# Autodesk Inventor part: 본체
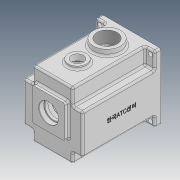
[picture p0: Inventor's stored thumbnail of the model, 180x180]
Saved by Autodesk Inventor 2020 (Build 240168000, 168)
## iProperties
Created: 2022-01
Part Number: 본체
Material: 일반
Document SubType Name: Modeling
Designer: user
Density: 1 g/cm^3
Appearance: 기본값
Author: user
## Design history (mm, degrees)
sketch "스케치2"
  geometry: L1 (-49, 55)-(49, 55); L2 (49, 55)-(49, -55); L3 (49, -55)-(-49, -55); L4 (-49, -55)-(-49, 55); L5 (-49, 55)-(49, -55); L6 (49, 55)-(-49, -55); 1 further point
  constraints: 12 end point, 2 midpoint, 2 parallel, 1 horizontal, 1 perpendicular
  dimensions: "d4" = 98 distance of L2.end L3.end; "d5" = 110 distance of L1.end L2.end
extrude "돌출2" new body sketch "스케치2" distance "d6" = 130; taper "d7" = 0 deg
sketch "스케치3"
  geometry: L1 (-49, 55)-(-33, 55); L2 (-33, 55)-(-33, 28); L3 (-33, 28)-(-49, 28); L4 (-49, 28)-(-49, 55); L5 (49, 55)-(33, 55); L6 (33, 55)-(33, 28); L7 (33, 28)-(49, 28); L8 (49, 28)-(49, 55); 1 further point
  constraints: 16 end point, 4 parallel, 2 horizontal, 2 perpendicular
  dimensions: "d8" = 16 distance of L1.start L1.end; "d9" = 16 distance of L5.start L5.end; "d10" = 27 distance of L7.end L5.start; "d11" = 27 distance of L1.end L2.end
extrude "돌출3" cut sketch "스케치3" distance "d12" = 120; taper "d13" = 0 deg
sketch "스케치4"
  geometry: L1 (-49, -55)-(49, -55) reference; L2 (-49, -55)-(-33, -55); L3 (-33, -55)-(-33, -38); L4 (-33, -38)-(-49, -38); L5 (-49, -38)-(-49, -55); L6 (49, -55)-(33, -55); L7 (33, -55)-(33, -38); L8 (33, -38)-(49, -38); L9 (49, -38)-(49, -55); 3 further points
  constraints: 16 end point, 4 parallel, 2 horizontal, 2 perpendicular, 1 point on line
  dimensions: "d14" = 16 distance of L3.end L4.end; "d15" = 16 distance of L7.end L8.end; "d16" = 17 distance of L6.end L7.end
extrude "돌출4" cut sketch "스케치4" distance "d17" = 120; taper "d18" = 0 deg
node "작업 평면1"
sketch "스케치6"
  geometry: L1 (0, 0)-(0, 40); L2 (0, 40)-(0, 89); C1 r 22.5 at (0, 40)
  constraints: 4 end point, 2 vertical, 1 centre point, 1 coincident
  dimensions: "d24" = 40 distance of L1.start L1.end; "d25" = 45 diameter of C1; "d26" = 49 distance of L2.start L2.end
extrude "돌출6" join sketch "스케치6" stored distance "d28" = 7; taper "d29" = 0 deg
node "작업 평면2"
sketch "스케치7"
  geometry: L1 (0, 0)-(0, 40); L2 (0, 40)-(0, 89); C1 r 15 at (0, 89)
  constraints: 4 end point, 1 centre point, 1 coincident, 1 point on line, 1 vertical
  dimensions: "d31" = 40 distance of L1.start L1.end; "d32" = 49 distance of L1.end L2.end; "d33" = 30 diameter of C1
extrude "돌출7" join sketch "스케치7" stored distance "d34" = 7; taper "d35" = 0 deg
sketch "스케치8"
  geometry: L1 (49, -55)-(-49, -55) reference; L2 (-23, 45)-(23, 45); L3 (23, 45)-(23, -5); L4 (23, -5)-(-23, -5); L5 (-23, -5)-(-23, 45); L6 (-49, 55)-(49, 55) reference; L7 (-49, -55)-(-49, 55) reference; L8 (49, -55)-(-49, -55) reference; L9 (49, 55)-(49, -55) reference; L10 (-49, 55)-(49, 55) reference; C1 r 42 at (0, -5); 6 further points
  constraints: 8 end point, 4 midpoint, 2 parallel, 2 vertical alignment, 1 centre point, 1 coincident, 1 horizontal, 1 perpendicular
  dimensions: "d38" = 50 distance from line of L1 C1.centre; "d39" = 84 diameter of C1; "d40" = 50 distance of C1.centre point (0, 45); "d41" = 46 distance between parallel lines of L5 L3
extrude "돌출8" cut sketch "스케치8" distance "d42" = 121; taper "d43" = 0 deg
sketch "스케치10"
  geometry: L1 (-23, 45)-(23, 45) reference; L2 (-23, 30.143)-(-23, 45) reference; L3 (23, 45)-(23, 30.143) reference; L4 (-26, 31.729)-(-26, 48); L5 (-26, 48)-(26, 48); L6 (26, 48)-(26, 31.729); A1 r 42 centre (0, -5) between (-23, 30.143) and (23, 30.143) reference; A2 r 45 centre (0, -5) between (-26, 31.729) and (26, 31.729); 1 further point
  constraints: 6 end point, 2 point on circle, 1 centre point, 3 other
  dimensions: "d50" = 3 radial gap between concentric circles of A1 A2
extrude "돌출10" cut sketch "스케치10" distance "d51" = 9; taper "d52" = 0 deg
sketch "스케치11"
  geometry: C1 r 22.5 at (0, 0) reference; 2 further points
  constraints: 1 coincident
hole "구멍1" sketch "스케치11" at (0, 0) diameter "d53" = 33.376; stored, may be unused: countersink angle "d57" = 90 deg, drill point angle "d59" = 0 deg; dims "d54" = 70, "d55" = 4, "d56" = 2, "d58" = 77.3
sketch "스케치12"
  geometry: L1 (-27, 33)-(27, 33); L2 (27, 33)-(27, -21); L3 (27, -21)-(-27, -21); L4 (-27, -21)-(-27, 33); L5 (-27, 33)-(27, -21); L6 (27, 33)-(-27, -21); L7 (-33, -55)-(33, -55) reference; 3 further points
  constraints: 12 end point, 3 midpoint, 2 parallel, 1 horizontal, 1 perpendicular, 1 vertical alignment
  dimensions: "d60" = 54 distance of L2.end L3.end; "d61" = 54 distance of L1.end L2.end; "d62" = 61 distance from line of L7 point (0, 6)
extrude "돌출11" join sketch "스케치12" distance "d63" = 7; taper "d64" = 0 deg
sketch "스케치13"
  geometry: C1 r 15 at (0, 0) reference; 2 further points
  constraints: 1 coincident
hole "구멍2" sketch "스케치13" at (0, 0) diameter "d65" = 20; stored, may be unused: countersink angle "d69" = 90 deg, drill point angle "d71" = 0 deg; dims "d66" = 70, "d67" = 4, "d68" = 2, "d70" = 51.3
sketch "스케치15"
  geometry: C1 r 10 at (23, -32) reference; C2 r 15 at (23, -32); 1 further point
  constraints: 1 centre point, 1 coincident
  dimensions: "d72" = 30 diameter of C2
extrude "돌출12" cut sketch "스케치15" distance "d73" = 5; taper "d74" = 0 deg
chamfer "모따기1" distance "d75" = 1; stored, may be unused: second distance "d76" = 2, angle "d77" = 45 deg
sketch "스케치21"
  geometry: L1 (0, 6)-(0, -25); A1 r 21 centre (0, 6) between (8.978, -12.984) and (-8.978, -12.984); A2 r 15 centre (0, -25) between (-8.978, -12.984) and (8.978, -12.984); 1 further point
  constraints: 4 point on circle, 2 centre point, 2 coincident, 2 end point, 1 vertical
  dimensions: "d92" = 42 diameter of A1; "d93" = 31 distance of L1.start L1.end; "d94" = 30 diameter of A2
extrude "돌출16" join sketch "스케치21" distance "d95" = 7; taper "d96" = 0 deg
sketch "스케치22"
  geometry: A1 r 21 centre (0, 6) between (8.978, -12.984) and (-8.978, -12.984) reference; 2 further points
  constraints: 1 coincident
hole "구멍3" sketch "스케치22" at (0, 6) diameter "d97" = 28; stored, may be unused: countersink angle "d101" = 90 deg, drill point angle "d103" = 0 deg; dims "d98" = 70, "d99" = 35, "d100" = 10, "d102" = 51.3
sketch "스케치23"
  geometry: C1 r 14 at (0, 6) reference; C2 r 16 at (0, 6); 1 further point
  constraints: 1 centre point, 1 coincident
  dimensions: "d104" = 32 diameter of C2
extrude "돌출17" cut sketch "스케치23" distance "d105" = 8.3; taper "d106" = 0 deg
sketch "스케치25"
  geometry: A1 r 15 centre (0, -25) between (-8.978, -12.984) and (8.978, -12.984) reference; 2 further points
  constraints: 1 coincident
hole "구멍4" sketch "스케치25" at (0, -25) diameter "d107" = 19; stored, may be unused: countersink angle "d111" = 90 deg, drill point angle "d113" = 0 deg; dims "d108" = 70, "d109" = 22, "d110" = 7, "d112" = 10
chamfer "모따기2" distance "d114" = 1; stored, may be unused: second distance "d115" = 2, angle "d116" = 45 deg
sketch "스케치26"
  geometry: L1 (-36, -5)-(36, -5); L2 (-36, -1)-(-41.809, -1); L3 (-35.778, -8.994)-(-41.81, -8.994); L4 (35.778, -1.006)-(41.81, -1.006); L5 (35.778, -8.994)-(41.81, -8.994); A1 r 42 centre (0, -5) between (-23, 30.143) and (23, 30.143) reference; A2 r 36 centre (0, -5) between (-36, -5) and (36, -5); A3 r 4 centre (-36, -5) between (-36, -1) and (-35.778, -8.994); A4 r 4 centre (36, -5) between (35.778, -1.006) and (35.778, -8.994); A5 r 42 centre (0, -5) between (-23, 30.143) and (23, 30.143) reference; 8 further points
  constraints: 14 point on circle, 10 end point, 4 horizontal, 3 centre point, 2 coincident, 1 parallel
  dimensions: "d119" = 72 diameter of A2; "d120" = 8 diameter of A3; "d121" = 8 diameter of A4
extrude "돌출18" join sketch "스케치26" stored distance "d122" = 7; taper "d123" = 0 deg
sketch "스케치27"
  geometry: A1 r 4 centre (-36, -5) between (-36.222, -8.994) and (-36, -1) reference; A2 r 4 centre (36, -5) between (36.222, -1.006) and (36.222, -8.994) reference; 3 further points
  constraints: 2 coincident
hole "구멍5" sketch "스케치27" at (-36, -5), (36, -5) diameter "d124" = 3.242; stored, may be unused: countersink angle "d128" = 90 deg, drill point angle "d130" = 118 deg; dims "d125" = 7, "d126" = 22, "d127" = 7, "d129" = 9
fillet "모깎기3" dims "d131" = 3
fillet "모깎기4" dims "d132" = 3
fillet "모깎기5" dims "d133" = 3
fillet "모깎기6" dims "d134" = 3
fillet "모깎기7" dims "d135" = 3
fillet "모깎기8" dims "d136" = 3
fillet "모깎기9" dims "d137" = 3
fillet "모깎기10" dims "d138" = 3
fillet "모깎기11" dims "d139" = 3
fillet "모깎기12" dims "d140" = 3
fillet "모깎기13" dims "d144" = 0.3
fillet "모깎기14" dims "d145" = 6
fillet "모깎기15" dims "d146" = 3
fillet "모깎기16" dims "d147" = 3
fillet "모깎기17" dims "d148" = 6
chamfer "모따기4" distance "d149" = 1; stored, may be unused: second distance "d150" = 2, angle "d151" = 30 deg
fillet "모깎기18" dims "d152" = 3
fillet "모깎기19" dims "d153" = 3
fillet "모깎기20" dims "d154" = 3
fillet "모깎기21" dims "d155" = 3
sketch "스케치28"
  geometry: L1 (-49, -52)-(-49, 52) reference; L2 (-46, 55)-(46, 55) reference; L3 (-42, 48)-(-42, -48); L4 (0, 55)-(0, -55); 4 further points
  constraints: 4 end point, 2 symmetric about line, 2 vertical, 1 coincident, 1 midpoint
  dimensions: "d157" = 7 distance from line of L1 L3.start; "d158" = 7 distance from line of L2 L3.start; "d159" = 96 distance of L3.start L3.end
hole "구멍6" sketch "스케치28" at (-42, 48), (-42, -48), (42, 48), (42, -48) diameter "d160" = 7; stored, may be unused: countersink angle "d164" = 90 deg, drill point angle "d166" = 118 deg; dims "d161" = 7, "d162" = 22, "d163" = 7, "d165" = 9
sketch "스케치30"
  geometry: L1 (-3, 87)-(-3, 66) reference; L2 (114, 90)-(0, 90) reference; L3 (114, 63)-(0, 63) reference; 2 further points
  constraints: 1 other
  dimensions: "d167" = 65 distance from line of L1 point (62, 30); "d173" = 27 distance between parallel lines of L3 L2 (derived); "d174" = 33 distance from line of point (62, 30) L3
feature "엠보싱1" sketch "스케치30" dims "d171" = 0.5, "d172" = 0
fillet "모깎기23" dims "d176" = 0.3
fillet "모깎기24" dims "d177" = 3
chamfer "모따기5" distance "d178" = 0.8; stored, may be unused: second distance "d179" = 2, angle "d180" = 30 deg
node "솔리드2"
node "투영된 루프1"
node "투영된 루프2"
feature "A9D066F2-1C7D-4E18-AEED-F7BC21143FA4" dims "d65" = 20, "d66" = 70, "d67" = 4, "d68" = 2, "d69" = 90 deg, "d70" = 51.3, "d71" = 0
other parameters: "d23" = 65, "d30" = -5
